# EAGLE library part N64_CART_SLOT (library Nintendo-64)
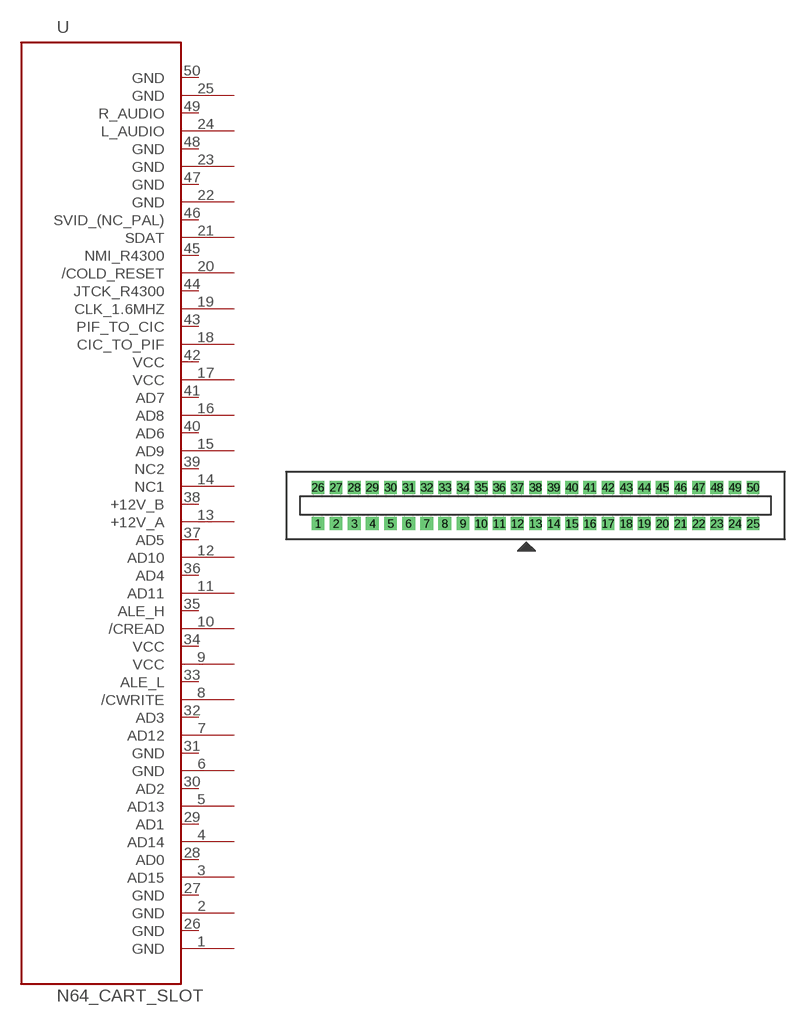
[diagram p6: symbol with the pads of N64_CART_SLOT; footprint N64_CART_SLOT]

Designator prefix -

## N64_CART_SLOT  [N64_CART_SLOT]
1  GND  pwr
2  GND  pwr
3  AD15
4  AD14
5  AD13
6  GND  pwr
7  AD12
8  /CWRITE  in
9  VCC  pwr
10  /CREAD  in
11  AD11
12  AD10
13  +12V_A  pwr
14  NC1  nc
15  AD9
16  AD8
17  VCC  pwr
18  CIC_TO_PIF  out
19  CLK_1.6MHZ  in
20  /COLD_RESET  in
21  SDAT
22  GND  pwr
23  GND  pwr
24  L_AUDIO  out
25  GND  pwr
26  GND  pwr
27  GND  pwr
28  AD0
29  AD1
30  AD2
31  GND  pwr
32  AD3
33  ALE_L  in
34  VCC  pwr
35  ALE_H  in
36  AD4
37  AD5
38  +12V_B  pwr
39  NC2  nc
40  AD6
41  AD7
42  VCC  pwr
43  PIF_TO_CIC  in
44  JTCK_R4300  out
45  NMI_R4300  out
46  SVID_(NC_PAL)  in
47  GND  pwr
48  GND  pwr
49  R_AUDIO  out
50  GND  pwr

## Footprint N64_CART_SLOT (pad centres in mm)
drill 1.2 pad 1.778 square: 1 -29.21,-2.54; 2 -26.67,-2.54; 3 -24.13,-2.54; 4 -21.59,-2.54; 5 -19.05,-2.54; 6 -16.51,-2.54; 7 -13.97,-2.54; 8 -11.43,-2.54; 9 -8.89,-2.54; 10 -6.35,-2.54; 11 -3.81,-2.54; 12 -1.27,-2.54; 13 1.27,-2.54; 14 3.81,-2.54; 15 6.35,-2.54; 16 8.89,-2.54; 17 11.43,-2.54; 18 13.97,-2.54; 19 16.51,-2.54; 20 19.05,-2.54; 21 21.59,-2.54; 22 24.13,-2.54; 23 26.67,-2.54; 24 29.21,-2.54; 25 31.75,-2.54; 26 -29.21,2.54; 27 -26.67,2.54; 28 -24.13,2.54; 29 -21.59,2.54; 30 -19.05,2.54; 31 -16.51,2.54; 32 -13.97,2.54; 33 -11.43,2.54; 34 -8.89,2.54; 35 -6.35,2.54; 36 -3.81,2.54; 37 -1.27,2.54; 38 1.27,2.54; 39 3.81,2.54; 40 6.35,2.54; 41 8.89,2.54; 42 11.43,2.54; 43 13.97,2.54; 44 16.51,2.54; 45 19.05,2.54; 46 21.59,2.54; 47 24.13,2.54; 48 26.67,2.54; 49 29.21,2.54; 50 31.75,2.54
